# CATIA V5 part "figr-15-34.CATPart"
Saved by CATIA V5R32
Part number: Part1
Bounding box of the stored display mesh (mm): x -40.264 to 42.014, y -25.445 to 25.445, z -51 to 0.75
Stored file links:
  D:\PROJECTS\Project 2022\CATIA V5 6R 2022\Resources\Part Files\c15_catia_v5_6r2022_prt\figr-15-34.CATPart
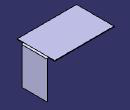
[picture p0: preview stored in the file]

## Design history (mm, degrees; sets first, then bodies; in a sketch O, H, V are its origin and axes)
SheetMetalParameters1: Thickness 0.75, BendRadius 1, KFactor 0.356492 {= log(min(100,max(20*SheetMetalParameters1.BendRadius,SheetMetalParameters1.Thickness)/SheetMetalParameters1.Thickness))/log(100)/2}, ReliefRadialLength 1, ReliefAxialLength 2, MinimumBendRadius 0
Body1 (main body)
  Sketch1 on xy-plane, origin (0, 0, 0), H (1, 0, 0), V (0, 1, 0)
    line L1 (-40.2643, 25.445) -> (40.2643, 25.445)
    line L2 (40.2643, 25.445) -> (40.2643, -25.445)
    line L3 (40.2643, -25.445) -> (-40.2643, -25.445)
    line L4 (-40.2643, -25.445) -> (-40.2643, 25.445)
    horizontal: L1 H, L3 H
    vertical: L2 V, L4 V
    symmetry: L1 L3 H, L4 L2 V
  Wall1: Thickness 0.75, Profile Sketch1
  Plane1: type Offset, RefPlane zx-plane, Offset 17
  Plane2: type Offset, RefPlane zx-plane, Offset 17, reversed
  Flange1: Angle 90, Length 50, Radius 1, KFacteur 0.356492 {= log(min(100,max(20*Flange1.Radius,SheetMetalParameters1.Thickness)/SheetMetalParameters1.Thickness))/log(100)/2}, Guide edge [face of Wall1 | face of Wall1], Limit1 Plane1, Limit2 Plane2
